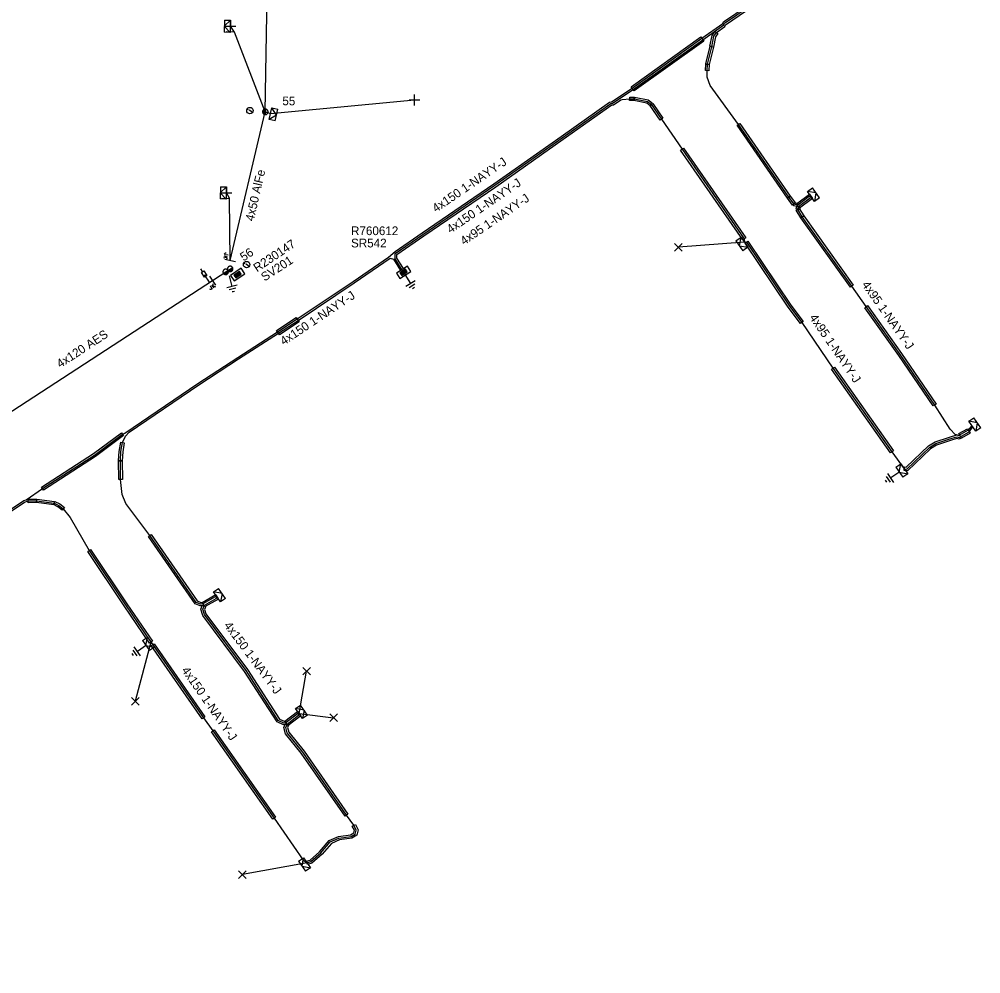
# Model space of a CAD drawing. Extents: x -544780 to -541582, y -1198995 to -1196551.
# Drawn here: x -543671.3 to -543561, y -1197426 to -1197316.4 of the extents above; entities that cross this region are included whole.
import ezdxf

# ---------------------------------------------------------------- set-up
doc = ezdxf.new("R2010")
doc.units = 0
for name, color, linetype in [('Vrstva 1', 7, 'Continuous'), ('Vrstva 10', 7, 'Continuous'), ('Vrstva 13', 7, 'Continuous'), ('Vrstva 14', 7, 'Continuous'), ('Vrstva 15', 7, 'Continuous'), ('Vrstva 16', 7, 'Continuous'), ('Vrstva 18', 7, 'Continuous'), ('Vrstva 2', 7, 'Continuous'), ('Vrstva 20', 7, 'Continuous'), ('Vrstva 28', 7, 'Continuous'), ('Vrstva 29', 7, 'Continuous'), ('Vrstva 30', 7, 'Continuous'), ('Vrstva 31', 7, 'Continuous'), ('Vrstva 34', 7, 'Continuous'), ('Vrstva 36', 7, 'Continuous'), ('Vrstva 5', 7, 'Continuous'), ('Vrstva 50', 7, 'Continuous'), ('Vrstva 51', 7, 'Continuous'), ('Vrstva 54', 7, 'Continuous'), ('Vrstva 59', 7, 'Continuous'), ('Vrstva 6', 7, 'Continuous'), ('Vrstva 8', 7, 'Continuous'), ('Vrstva 9', 7, 'Continuous')]:
    doc.layers.add(name, color=color, linetype=linetype)

# ---------------------------------------------------------------- blocks, each defined once
blk = doc.blocks.new('NN440')
at = {"layer": 'Vrstva 2'}
for points in [[(0.63, 0), (0.63, 0.06), (0.62, 0.13), (0.6, 0.19), (0.58, 0.25), (0.55, 0.31), (0.51, 0.37), (0.47, 0.42), (0.42, 0.46), (0.37, 0.51), (0.32, 0.54), (0.26, 0.57), (0.2, 0.59), (0.13, 0.61), (0.07, 0.62), (0, 0.63), (-0.06, 0.62), (-0.13, 0.61), (-0.19, 0.59), (-0.26, 0.57), (-0.31, 0.54), (-0.37, 0.51), (-0.42, 0.46), (-0.47, 0.42), (-0.51, 0.37), (-0.54, 0.31), (-0.57, 0.25), (-0.6, 0.19), (-0.62, 0.13), (-0.63, 0.06), (-0.63, 0), (-0.63, -0.07), (-0.62, -0.14), (-0.6, -0.2), (-0.57, -0.26), (-0.54, -0.32), (-0.51, -0.37), (-0.47, -0.43), (-0.42, -0.47), (-0.37, -0.51), (-0.31, -0.55), (-0.26, -0.58), (-0.19, -0.6), (-0.13, -0.62), (-0.06, -0.63), (0, -0.63), (0.07, -0.63), (0.13, -0.62), (0.2, -0.6), (0.26, -0.58), (0.32, -0.55), (0.37, -0.51), (0.42, -0.47), (0.47, -0.43), (0.51, -0.37), (0.55, -0.32), (0.58, -0.26), (0.6, -0.2), (0.62, -0.14), (0.63, -0.07), (0.63, 0)], [(-0.63, 0), (0.63, 0)], [(-0.6, -0.18), (0.57, -0.18)], [(-0.51, -0.32), (0.5, -0.32)], [(-0.37, -0.47), (0.35, -0.47)]]:
    blk.add_lwpolyline(points, dxfattribs=at)
blk = doc.blocks.new('NN450')
at = {"layer": 'Vrstva 2'}
for points in [[(0, 0), (0, 0.07), (-0.01, 0.13), (-0.03, 0.19), (-0.05, 0.25), (-0.08, 0.31), (-0.12, 0.37), (-0.16, 0.42), (-0.21, 0.46), (-0.26, 0.51), (-0.31, 0.54), (-0.37, 0.57), (-0.43, 0.59), (-0.5, 0.61), (-0.56, 0.62), (-0.63, 0.62), (-0.69, 0.62), (-0.75, 0.61), (-0.82, 0.59), (-0.88, 0.57), (-0.94, 0.54), (-0.99, 0.51), (-1.04, 0.46), (-1.09, 0.42), (-1.13, 0.37), (-1.17, 0.31), (-1.2, 0.25), (-1.22, 0.19), (-1.24, 0.13), (-1.25, 0.07), (-1.25, 0), (-1.25, -0.07), (-1.24, -0.13), (-1.22, -0.19), (-1.2, -0.25), (-1.17, -0.31), (-1.13, -0.37), (-1.09, -0.42), (-1.04, -0.46), (-0.99, -0.51), (-0.94, -0.54), (-0.88, -0.57), (-0.82, -0.59), (-0.75, -0.61), (-0.69, -0.62), (-0.62, -0.63), (-0.56, -0.62), (-0.5, -0.61), (-0.43, -0.59), (-0.37, -0.57), (-0.31, -0.54), (-0.26, -0.51), (-0.21, -0.46), (-0.16, -0.42), (-0.12, -0.37), (-0.08, -0.31), (-0.05, -0.25), (-0.03, -0.19), (-0.01, -0.13), (0, -0.07), (0, 0)], [(1.25, 0), (1.25, 0.07), (1.24, 0.13), (1.22, 0.19), (1.2, 0.25), (1.17, 0.31), (1.13, 0.37), (1.09, 0.42), (1.04, 0.46), (0.99, 0.51), (0.94, 0.54), (0.88, 0.57), (0.82, 0.59), (0.75, 0.61), (0.69, 0.62), (0.62, 0.62), (0.56, 0.62), (0.5, 0.61), (0.43, 0.59), (0.37, 0.57), (0.31, 0.54), (0.26, 0.51), (0.21, 0.46), (0.16, 0.42), (0.12, 0.37), (0.08, 0.31), (0.05, 0.25), (0.03, 0.19), (0.01, 0.13), (0, 0.07), (0, 0), (0, -0.07), (0.01, -0.13), (0.03, -0.19), (0.05, -0.25), (0.08, -0.31), (0.12, -0.37), (0.16, -0.42), (0.21, -0.46), (0.26, -0.51), (0.31, -0.54), (0.37, -0.57), (0.43, -0.59), (0.5, -0.61), (0.56, -0.62), (0.63, -0.63), (0.69, -0.62), (0.75, -0.61), (0.82, -0.59), (0.88, -0.57), (0.94, -0.54), (0.99, -0.51), (1.04, -0.46), (1.09, -0.42), (1.13, -0.37), (1.17, -0.31), (1.2, -0.25), (1.22, -0.19), (1.24, -0.13), (1.25, -0.07), (1.25, 0)], [(-1.25, 0), (1.25, 0)], [(-1.23, -0.16), (-0.02, -0.16)], [(-1.16, -0.32), (-0.09, -0.32)], [(-1.03, -0.47), (-0.22, -0.47)], [(0.02, -0.16), (1.23, -0.16)], [(0.09, -0.32), (1.16, -0.32)], [(0.22, -0.47), (1.03, -0.47)]]:
    blk.add_lwpolyline(points, dxfattribs=at)
blk = doc.blocks.new('NN840')
at = {"layer": 'Vrstva 15'}
for points in [[(0, 0.62), (0, -0.63)], [(-0.75, -0.71), (-0.75, -0.66)], [(-0.73, -0.76), (-0.75, -0.71)], [(-0.66, -0.8), (-0.73, -0.76)], [(-0.63, -0.8), (-0.66, -0.8)], [(-0.56, -0.76), (-0.63, -0.8)], [(-0.54, -0.71), (-0.56, -0.76)], [(-0.54, -0.38), (-0.54, -0.71)], [(-0.33, -0.38), (-0.33, -0.8)], [(-0.33, -0.64), (-0.13, -0.38)], [(-0.26, -0.56), (-0.09, -0.8)]]:
    blk.add_lwpolyline(points, dxfattribs=at)
blk = doc.blocks.new('NN770')
at = {"layer": 'Vrstva 10'}
for p, q in [((0, 0.19), (0, 0.26)), ((0, -0.28), (0, 0.11))]:
    blk.add_line(p, q, dxfattribs=at)
blk.add_circle((0, -0.01), 0.375, dxfattribs=at)
blk = doc.blocks.new('NN800')
at = {"layer": 'Vrstva 1'}
for points in [[(-0.44, 0.44), (0.44, -0.44)], [(-0.44, -0.44), (0.44, 0.44)]]:
    blk.add_lwpolyline(points, dxfattribs=at)
blk = doc.blocks.new('NN820')
at = {"layer": 'Vrstva 13'}
for points in [[(0, 0), (0, -1.05)], [(-0.16, -0.81), (0.16, -0.81)], [(-0.16, -1.47), (-0.16, -0.81)], [(0, -1.05), (-0.06, -0.93)], [(0, -1.05), (0.06, -0.93)], [(0.16, -0.81), (0.16, -1.47)], [(0.16, -1.47), (-0.16, -1.47)], [(0, -1.47), (0, -1.87)]]:
    blk.add_lwpolyline(points, dxfattribs=at)
blk = doc.blocks.new('NN620')
at = {"layer": 'Vrstva 8'}
for points in [[(0.75, 0), (-0.75, 0)], [(-0.75, 0), (-0.75, -0.75)], [(0.75, -0.75), (0.75, 0)], [(-0.75, -0.75), (0.75, -0.75)], [(0.37, -0.18), (-0.38, -0.18)], [(-0.38, -0.18), (-0.38, -0.56)], [(-0.38, -0.56), (0.37, -0.56)], [(0.32, -0.23), (-0.33, -0.23)], [(-0.33, -0.23), (-0.33, -0.51)], [(-0.33, -0.51), (0.32, -0.51)], [(0.27, -0.27), (-0.28, -0.27)], [(-0.28, -0.27), (-0.28, -0.46)], [(-0.28, -0.46), (0.27, -0.46)], [(0.23, -0.32), (-0.23, -0.32)], [(-0.23, -0.32), (-0.23, -0.42)], [(-0.23, -0.42), (0.23, -0.42)], [(-0.19, -0.37), (0.19, -0.37)], [(0.23, -0.42), (0.23, -0.32)], [(0.27, -0.46), (0.27, -0.27)], [(0.32, -0.51), (0.32, -0.23)], [(0.37, -0.56), (0.37, -0.18)]]:
    blk.add_lwpolyline(points, dxfattribs=at)
blk = doc.blocks.new('NN630')
at = {"layer": 'Vrstva 9'}
for points in [[(0, -0.7), (-0.7, 0)], [(-0.7, -0.7), (-0.7, 0), (0.7, 0), (0.7, -0.7)], [(-0.7, -0.7), (0.7, -0.7)], [(0, -0.7), (0.7, 0)]]:
    blk.add_lwpolyline(points, dxfattribs=at)
blk = doc.blocks.new('NN810')
at = {"layer": 'Vrstva 14'}
for points in [[(0, -0.64), (0, -1.89)], [(0.63, -1.89), (-0.62, -1.89)], [(0.39, -2.2), (-0.4, -2.2)], [(0, -2.52), (-0.12, -2.52)], [(0.14, -2.52), (0, -2.52)]]:
    blk.add_lwpolyline(points, dxfattribs=at)
blk = doc.blocks.new('NN510')
at = {"layer": 'Vrstva 2'}
blk.add_lwpolyline([(0, 0), (0, 0.94)], dxfattribs=at)

msp = doc.modelspace()

# ---------------------------------------------------------------- linework, layer by layer
at = {"layer": 'Vrstva 1'}
for points in [[(-543643.09, -1197327.06), (-543642.64, -1197300.18)], [(-543647.12, -1197344.15), (-543643.09, -1197327.06)]]:
    msp.add_lwpolyline(points, dxfattribs=at)
at = {"layer": 'Vrstva 20'}
for points in [[(-543601.09, -1197324.18), (-543593.09, -1197318.46), (-543592.75, -1197318.94), (-543600.75, -1197324.66)], [(-543592.04, -1197319.54), (-543591.79, -1197318.3), (-543591.48, -1197317.83), (-543591.15, -1197318.05), (-543591.41, -1197318.46), (-543591.64, -1197319.62)], [(-543591.65, -1197319.63), (-543592.13, -1197321.64), (-543592.51, -1197321.54), (-543592.03, -1197319.53)], [(-543592.57, -1197322.33), (-543592.52, -1197321.58), (-543592.12, -1197321.6), (-543592.17, -1197322.35)], [(-543601.25, -1197325.36), (-543600.72, -1197325.38), (-543600.74, -1197325.78), (-543601.27, -1197325.76)], [(-543600.69, -1197325.38), (-543599.14, -1197325.7), (-543598.66, -1197326.04), (-543598.9, -1197326.36), (-543599.3, -1197326.08), (-543600.77, -1197325.78)], [(-543598.62, -1197326.09), (-543597.45, -1197327.79), (-543597.77, -1197328.01), (-543598.94, -1197326.31)], [(-543583.16, -1197336.97), (-543588.92, -1197328.61), (-543588.6, -1197328.39), (-543582.84, -1197336.75)], [(-543595.09, -1197331.24), (-543587.94, -1197341.55), (-543588.26, -1197341.77), (-543595.41, -1197331.46)], [(-543582.84, -1197336.74), (-543582.23, -1197337.55), (-543582.55, -1197337.79), (-543583.16, -1197336.98)], [(-543582.34, -1197337.48), (-543581.96, -1197337.57), (-543582.05, -1197337.95), (-543582.44, -1197337.86)], [(-543582.11, -1197337.62), (-543580.63, -1197336.53), (-543580.27, -1197337.01), (-543581.75, -1197338.11)], [(-543582.15, -1197338.22), (-543582.07, -1197337.9), (-543581.69, -1197338), (-543581.77, -1197338.32)], [(-543581.61, -1197339.22), (-543582.13, -1197338.37), (-543581.79, -1197338.17), (-543581.27, -1197339.02)], [(-543575.92, -1197347.2), (-543581.6, -1197339.24), (-543581.28, -1197339), (-543575.6, -1197346.96)], [(-543587.68, -1197341.92), (-543582.75, -1197349.25), (-543581.34, -1197351.13), (-543581.66, -1197351.37), (-543583.07, -1197349.49), (-543588.02, -1197342.14)], [(-543566.41, -1197360.84), (-543570.37, -1197355.03), (-543574.27, -1197349.55), (-543573.95, -1197349.31), (-543570.05, -1197354.81), (-543566.07, -1197360.62)], [(-543641.79, -1197352.16), (-543639.55, -1197350.68), (-543639.21, -1197351.18), (-543641.45, -1197352.66)], [(-543577.76, -1197356.37), (-543570.99, -1197365.98), (-543571.31, -1197366.22), (-543578.08, -1197356.61)], [(-543668.78, -1197370.16), (-543662.81, -1197366.31), (-543659.6, -1197363.92), (-543659.36, -1197364.24), (-543662.59, -1197366.63), (-543668.56, -1197370.5)], [(-543563.48, -1197364), (-543562.49, -1197363.45), (-543562.19, -1197363.97), (-543563.18, -1197364.52)], [(-543659.28, -1197365.07), (-543659.46, -1197366.09), (-543659.53, -1197367.13), (-543659.93, -1197367.11), (-543659.86, -1197366.05), (-543659.68, -1197365.01)], [(-543569.7, -1197367.84), (-543569.51, -1197367.87), (-543566.97, -1197365.43), (-543566.19, -1197364.96), (-543564.55, -1197364.42), (-543563.71, -1197364.17), (-543563.47, -1197364.22), (-543563.38, -1197364.17), (-543563.19, -1197364.52), (-543563.42, -1197364.65), (-543563.7, -1197364.58), (-543564.43, -1197364.8), (-543566.03, -1197365.32), (-543566.73, -1197365.75), (-543569.37, -1197368.29), (-543569.76, -1197368.24)], [(-543659.9, -1197369.29), (-543659.93, -1197367.12), (-543659.53, -1197367.12), (-543659.5, -1197369.29)], [(-543670.3, -1197371.55), (-543669.34, -1197371.53), (-543669.34, -1197371.93), (-543670.3, -1197371.95)], [(-543669.31, -1197371.53), (-543667.31, -1197371.79), (-543667.37, -1197372.19), (-543669.37, -1197371.93)], [(-543667.26, -1197371.81), (-543666.67, -1197372.08), (-543666.16, -1197372.51), (-543666.42, -1197372.81), (-543666.89, -1197372.42), (-543667.42, -1197372.17)], [(-543650.24, -1197383.77), (-543650.56, -1197383.79), (-543651.16, -1197383.55), (-543656.5, -1197375.83), (-543656.18, -1197375.61), (-543650.9, -1197383.23), (-543650.5, -1197383.39), (-543650.27, -1197383.37)], [(-543663.14, -1197377.31), (-543658.97, -1197383.55), (-543656.05, -1197387.84), (-543656.39, -1197388.06), (-543659.31, -1197383.77), (-543663.48, -1197377.53)], [(-543650.35, -1197383.4), (-543648.78, -1197382.5), (-543648.48, -1197383.02), (-543650.06, -1197383.92)], [(-543640.69, -1197397.41), (-543640.99, -1197397.46), (-543641.74, -1197397.12), (-543645.46, -1197391.33), (-543650.26, -1197384.88), (-543650.49, -1197384.17), (-543650.29, -1197383.68), (-543649.92, -1197383.83), (-543650.07, -1197384.19), (-543649.9, -1197384.7), (-543645.14, -1197391.11), (-543641.46, -1197396.8), (-543640.93, -1197397.04), (-543640.76, -1197397.01)], [(-543655.86, -1197388.14), (-543650.03, -1197396.53), (-543650.35, -1197396.75), (-543656.18, -1197388.36)], [(-543640.85, -1197397.05), (-543639.39, -1197395.92), (-543639.03, -1197396.4), (-543640.48, -1197397.53)], [(-543648.95, -1197398.04), (-543641.91, -1197408.06), (-543642.23, -1197408.28), (-543649.27, -1197398.26)], [(-543633.92, -1197407.94), (-543638.96, -1197400.71), (-543640.76, -1197398.48), (-543640.95, -1197397.74), (-543640.78, -1197397.29), (-543640.4, -1197397.43), (-543640.53, -1197397.76), (-543640.4, -1197398.3), (-543638.64, -1197400.47), (-543633.6, -1197407.72)], [(-543638.36, -1197413.11), (-543637.95, -1197412.98), (-543636.86, -1197412.02), (-543635.75, -1197410.74), (-543634.69, -1197410.27), (-543633.3, -1197410.09), (-543632.94, -1197409.86), (-543632.86, -1197409.56), (-543633.1, -1197409.08), (-543632.74, -1197408.9), (-543632.44, -1197409.52), (-543632.6, -1197410.12), (-543633.16, -1197410.47), (-543634.59, -1197410.65), (-543635.51, -1197411.06), (-543636.58, -1197412.3), (-543637.75, -1197413.34), (-543638.24, -1197413.49)]]:
    msp.add_lwpolyline(points, close=True, dxfattribs=at)
at = {"layer": 'Vrstva 5'}
for points in [[(-543675.62, -1197374.92), (-543670.82, -1197371.69), (-543670.54, -1197371.61), (-543668.67, -1197370.33), (-543662.7, -1197366.47), (-543659.48, -1197364.08), (-543659.22, -1197363.95), (-543650.83, -1197358.24), (-543646.25, -1197355.28), (-543641.68, -1197352.33), (-543639.44, -1197350.85), (-543632.99, -1197346.55), (-543628.95, -1197343.76), (-543628.18, -1197343.11), (-543625.1, -1197340.97), (-543616.86, -1197335.34), (-543609.12, -1197329.9), (-543603.56, -1197325.94), (-543603.35, -1197325.92), (-543600.98, -1197324.34), (-543592.98, -1197318.62), (-543590.56, -1197316.92), (-543590.47, -1197316.74), (-543584.83, -1197312.86)], [(-543627.41, -1197345.18), (-543628.2, -1197343.93), (-543628.17, -1197343.34), (-543624.99, -1197341.13), (-543616.75, -1197335.5), (-543609.01, -1197330.06), (-543603.44, -1197326.1), (-543603.24, -1197326.08), (-543600.86, -1197324.5), (-543592.86, -1197318.78), (-543590.44, -1197317.08), (-543590.36, -1197316.9), (-543584.72, -1197313.02)], [(-543627.24, -1197345.07), (-543627.99, -1197343.88), (-543627.98, -1197343.45), (-543624.88, -1197341.29), (-543616.64, -1197335.66), (-543608.9, -1197330.22), (-543603.32, -1197326.26), (-543603.13, -1197326.25), (-543602.27, -1197325.68), (-543602.12, -1197325.63), (-543601.26, -1197325.56), (-543600.73, -1197325.58), (-543599.22, -1197325.89), (-543598.78, -1197326.2), (-543597.61, -1197327.9), (-543595.25, -1197331.35), (-543588.1, -1197341.66), (-543588.08, -1197342.04), (-543587.85, -1197342.03), (-543582.91, -1197349.37), (-543581.5, -1197351.25), (-543577.92, -1197356.49), (-543571.15, -1197366.1), (-543569.73, -1197368.04), (-543569.44, -1197368.08), (-543566.85, -1197365.59), (-543566.11, -1197365.14), (-543564.49, -1197364.61), (-543563.7, -1197364.37), (-543563.45, -1197364.44), (-543562.27, -1197363.79), (-543561.95, -1197363.36), (-543561.93, -1197363.16), (-543562.11, -1197363.24), (-543562.41, -1197363.63), (-543563.47, -1197364.23), (-543563.89, -1197364.12), (-543564.45, -1197363.51), (-543566.24, -1197360.73), (-543570.21, -1197354.92), (-543574.11, -1197349.43), (-543575.76, -1197347.08), (-543581.44, -1197339.12), (-543581.96, -1197338.27), (-543581.88, -1197337.95), (-543580.53, -1197336.95), (-543580.45, -1197336.77), (-543580.65, -1197336.79), (-543581.97, -1197337.77), (-543582.39, -1197337.67), (-543583, -1197336.86), (-543588.76, -1197328.5), (-543592.03, -1197324.03), (-543592.37, -1197323.1), (-543592.37, -1197322.34), (-543592.32, -1197321.59), (-543591.84, -1197319.58), (-543591.6, -1197318.38), (-543591.31, -1197317.94), (-543590.33, -1197317.25), (-543590.25, -1197317.07), (-543584.61, -1197313.18)], [(-543675.51, -1197375.08), (-543670.74, -1197371.87), (-543670.3, -1197371.75), (-543669.34, -1197371.73), (-543667.34, -1197371.99), (-543666.78, -1197372.25), (-543666.29, -1197372.66), (-543665.5, -1197373.66), (-543663.31, -1197377.42), (-543659.14, -1197383.66), (-543656.22, -1197387.95), (-543656.02, -1197388.25), (-543650.19, -1197396.64), (-543649.11, -1197398.15), (-543642.07, -1197408.17), (-543638.73, -1197413), (-543638.3, -1197413.3), (-543637.85, -1197413.16), (-543636.72, -1197412.16), (-543635.63, -1197410.9), (-543634.64, -1197410.46), (-543633.23, -1197410.28), (-543632.77, -1197409.99), (-543632.65, -1197409.54), (-543632.92, -1197408.99), (-543633.76, -1197407.83), (-543638.8, -1197400.59), (-543640.58, -1197398.39), (-543640.74, -1197397.75), (-543640.59, -1197397.36), (-543639.28, -1197396.34), (-543639.21, -1197396.16), (-543639.41, -1197396.18), (-543640.72, -1197397.21), (-543640.96, -1197397.25), (-543641.6, -1197396.96), (-543645.3, -1197391.22), (-543650.08, -1197384.79), (-543650.28, -1197384.18), (-543650.09, -1197383.71), (-543648.73, -1197382.93), (-543648.63, -1197382.76), (-543648.83, -1197382.76), (-543650.26, -1197383.57), (-543650.53, -1197383.59), (-543651.03, -1197383.39), (-543656.34, -1197375.72), (-543659.1, -1197372.05), (-543659.53, -1197371.02), (-543659.7, -1197369.29), (-543659.73, -1197367.12), (-543659.66, -1197366.07), (-543659.48, -1197365.04), (-543659.13, -1197364.3), (-543658.73, -1197363.85), (-543650.72, -1197358.4), (-543646.15, -1197355.44), (-543641.56, -1197352.49), (-543639.33, -1197351.01), (-543632.87, -1197346.71), (-543628.77, -1197343.88), (-543628.39, -1197343.99), (-543627.58, -1197345.29)]]:
    msp.add_lwpolyline(points, dxfattribs=at)
at = {"layer": 'Vrstva 50'}
msp.add_lwpolyline([(-543766.98, -1197426.04), (-543741.73, -1197407.43), (-543711.46, -1197387.37), (-543679.58, -1197366.23), (-543647.38, -1197345.27)], dxfattribs=at)
at = {"layer": 'Vrstva 54'}
for points in [[(-543643.09, -1197327.06), (-543646.64, -1197317.91), (-543647.1, -1197317.24)], [(-543643.09, -1197327.06), (-543642.48, -1197327.27)], [(-543647.12, -1197344.15), (-543647.21, -1197336.99), (-543647.56, -1197336.38)]]:
    msp.add_lwpolyline(points, dxfattribs=at)
at = {"layer": 'Vrstva 59'}
for points in [[(-543642.48, -1197327.27), (-543625.96, -1197325.7)], [(-543588.08, -1197342.04), (-543595.66, -1197342.61)], [(-543656.22, -1197387.95), (-543658.03, -1197394.75)], [(-543639.21, -1197396.16), (-543638.35, -1197391.29)], [(-543639.21, -1197396.16), (-543635.26, -1197396.64)], [(-543638.3, -1197413.3), (-543645.71, -1197414.64)]]:
    msp.add_lwpolyline(points, dxfattribs=at)

# ---------------------------------------------------------------- block references
at = {"layer": 'Vrstva 13'}
for p, rotation in [((-543646.64, -1197317.91), 88.7537333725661), ((-543647.17, -1197337.05), 88.48509162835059)]:
    msp.add_blockref('NN510', p, dxfattribs=dict(at, rotation=rotation))
for name, p, xscale, yscale, rotation in [('NN440', (-543643.09, -1197327.06), 0.49999999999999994, 0.4999999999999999, -90.94582225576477), ('NN450', (-543647.38, -1197345.27), 0.5, 0.5, 33.35263599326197)]:
    msp.add_blockref(name, p, dxfattribs=dict(at, xscale=xscale, yscale=yscale, rotation=rotation))
at = {"layer": 'Vrstva 15'}
for p, rotation in [((-543647.38, -1197345.27), 14.08049704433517), ((-543627.41, -1197345.18), 31.826961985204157), ((-543569.73, -1197368.04), -55.804995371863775), ((-543656.22, -1197387.95), -55.44547184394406)]:
    msp.add_blockref('NN810', p, dxfattribs=dict(at, rotation=rotation))
at = {"layer": 'Vrstva 16', "rotation": -146.79897228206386}
msp.add_blockref('NN820', (-543649.48, -1197346.64), dxfattribs=at)
at = {"layer": 'Vrstva 18'}
for p, rotation in [((-543647.12, -1197344.15), -102.92735558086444), ((-543649.17, -1197346.44), 33.20037501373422)]:
    msp.add_blockref('NN840', p, dxfattribs=dict(at, rotation=rotation))
at = {"layer": 'Vrstva 28'}
for p, rotation in [((-543646.47, -1197345.44), 33.79199998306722), ((-543627.41, -1197345.18), 33.02386839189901)]:
    msp.add_blockref('NN620', p, dxfattribs=dict(at, rotation=rotation))
at = {"layer": 'Vrstva 31'}
for p, rotation in [((-543647.1, -1197317.24), -91.24626669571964), ((-543642.48, -1197327.27), 77.07140829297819), ((-543647.56, -1197336.38), -91.51490837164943), ((-543580.45, -1197336.77), 124.69515407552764), ((-543588.08, -1197342.04), -55.30484594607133), ((-543561.93, -1197363.16), 124.69515405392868), ((-543569.73, -1197368.04), -55.304846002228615), ((-543648.63, -1197382.76), 124.69515407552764), ((-543656.22, -1197387.95), -55.3048458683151), ((-543639.21, -1197396.16), 124.69515399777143), ((-543638.3, -1197413.3), -55.304846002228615)]:
    msp.add_blockref('NN630', p, dxfattribs=dict(at, rotation=rotation))
at = {"layer": 'Vrstva 34'}
for p, rotation in [((-543647.1, -1197317.24), 45), ((-543625.96, -1197325.7), 45.00000009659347), ((-543647.56, -1197336.38), 45)]:
    msp.add_blockref('NN800', p, dxfattribs=dict(at, rotation=rotation))
for p in [(-543595.66, -1197342.61), (-543638.35, -1197391.29), (-543658.03, -1197394.75), (-543635.26, -1197396.64), (-543645.71, -1197414.64)]:
    msp.add_blockref('NN800', p, dxfattribs=at)
at = {"layer": 'Vrstva 36'}
for p, rotation in [((-543644.86, -1197326.92), 58.516302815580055), ((-543645.24, -1197344.6), 58.516302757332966)]:
    msp.add_blockref('NN770', p, dxfattribs=dict(at, rotation=rotation))

# ---------------------------------------------------------------- texts
at = {"layer": 'Vrstva 14'}
for s, rotation, p in [('55', 359.054, (-543641.14, -1197326.3)), ('56', 33.353, (-543645.58, -1197344.26))]:
    msp.add_text(s, height=1, rotation=rotation, dxfattribs=at).set_placement(p)
at = {"layer": 'Vrstva 2'}
msp.add_text('4x50 AlFe', height=1, rotation=77.071, dxfattribs=at).set_placement((-543644.43, -1197339.69))
at = {"layer": 'Vrstva 29'}
msp.add_text('R760612', height=1, dxfattribs=at).set_placement((-543633.25, -1197341.22))
msp.add_text('R230147', height=1, rotation=33.792, dxfattribs=at).set_placement((-543644.04, -1197345.5))
at = {"layer": 'Vrstva 30'}
msp.add_text('SR542', height=1, dxfattribs=at).set_placement((-543633.25, -1197342.63))
msp.add_text('SV201', height=1, rotation=33.084, dxfattribs=at).set_placement((-543643.17, -1197346.56))
at = {"layer": 'Vrstva 51'}
msp.add_text('4x120 AES', height=1, rotation=33.202, dxfattribs=at).set_placement((-543666.64, -1197356.52))
at = {"layer": 'Vrstva 6'}
for s, rotation, p in [('4x150 1-NAYY-J', 34.341, (-543623.5, -1197338.66)), ('4x150 1-NAYY-J', 34.343, (-543621.84, -1197341.07)), ('4x95 1-NAYY-J', 34.344, (-543620.28, -1197342.42)), ('4x95 1-NAYY-J', 305.074, (-543574.66, -1197346.91)), ('4x150 1-NAYY-J', 33.686, (-543640.97, -1197353.92)), ('4x95 1-NAYY-J', 304.341, (-543580.67, -1197350.69)), ('4x150 1-NAYY-J', 306.627, (-543647.89, -1197386.05)), ('4x150 1-NAYY-J', 304.794, (-543652.76, -1197391.19))]:
    msp.add_text(s, height=1, rotation=rotation, dxfattribs=at).set_placement(p)

doc.saveas('drawing.dxf')
